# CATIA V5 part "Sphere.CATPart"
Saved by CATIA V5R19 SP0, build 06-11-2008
Part number: Sphère
Bounding box of the stored display mesh (mm): x -3 to 3, y -2.946 to 2.946, z -15 to 2.5
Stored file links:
  G:\EU_thinkMotion\CFAO_2010\MMS_groupe3\MMS_groupe3\A reprendre\evulliez\evulliez\Sphere.CATPart
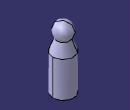
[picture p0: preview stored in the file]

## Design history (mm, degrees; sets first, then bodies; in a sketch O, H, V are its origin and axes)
Body1 (main body)
  Sketch1 on yz-plane, origin (0, 0, 0), H (0, 1, 0), V (0, 0, 1)
    line L1 (0, -2.5) -> (0, 2.5)
    point P1 (0, -2.5)
    arc A1 centre (0, 0) radius 2.5 from (0, -2.5) to (0, 2.5) ccw
    distance P1 H = 2.5
    coincidence: P1 V
    vertical: L1 V
  Shaft1: profile Sketch1, axis Z axis, angle 360
  Sketch2 on yz-plane, origin (0, 0, 0), H (0, 1, 0), V (0, 0, 1)
    line L1 (0, -1) -> (1.5, -1)
    point P1 (0, -1)
    point P2 (1.5, -1)
    line L2 (0, -1) -> (0, -5)
    point P3 (0, -5)
    line L3 (0, -5) -> (3, -5)
    point P4 (3, -5)
    line L4 (1.5, -1) -> (3, -5)
    distance P1 V = 0
    distance P1 H = 1
    distance P2 V = 1.5
    distance P3 H = 5
    distance P4 V = 3
    horizontal: L1 H, L3 H
    vertical: L2 V
  Shaft2: profile Sketch2, axis Z axis, angle 360
  Sketch3 on face of Shaft2 from Sketch2.L3, origin (0, 0, -5), H (1, 0, 0), V (0, -1, 0)
    circle A1 centre (0, 0) radius 3
    radius A1 = 3
  Pad1: profile Sketch3, direction (0, 0, -1), length 10
  Point1: (0, 0, 0)
  Line1: type PtDir, RefPoint Point1, Direction (1, 0, 0), Start -10, End 10
  Line2: type PtDir, RefPoint Point1, Direction (0, 1, 0), Start -10, End 10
